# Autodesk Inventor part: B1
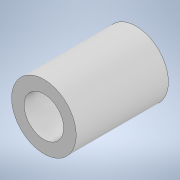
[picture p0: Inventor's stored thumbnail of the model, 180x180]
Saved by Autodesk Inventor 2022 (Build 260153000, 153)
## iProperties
Created: 2024-12
Part Number: B1
Material: 一般
Document SubType Name: Modeling
Designer: jsat7
Density: 1 g/cm^3
Appearance: 既定
Author: jsat7
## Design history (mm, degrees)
sketch "スケッチ1"
  geometry: C1 r 2.45 at (0, 0); C2 r 1.5 at (0, 0); 1 further point
  constraints: 2 centre point, 2 coincident
  dimensions: "d0" = 4.9 diameter of C1; "d1" = 3 diameter of C2
extrude "押し出し1" new body sketch "スケッチ1" distance "d2" = 7; taper "d3" = 0 deg
node "ソリッド1"
